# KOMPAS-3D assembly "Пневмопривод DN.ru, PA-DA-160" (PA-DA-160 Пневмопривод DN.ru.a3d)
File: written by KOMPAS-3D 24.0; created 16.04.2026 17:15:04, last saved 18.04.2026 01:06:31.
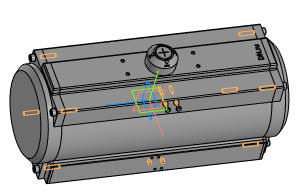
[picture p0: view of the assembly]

Document properties: Автор: DN.ru; Полное имя файла: C:\Работа\PA-DA-х Пневмопривод DN.ru\160\исходные материалы\PA-DA-160 Пневмопривод DN.ru.a3d

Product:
- Component [detail]: Пневмопривод DN.ru  | designation PA-DA-160  | qty 1  | pos. 1  | Масса: 20; Раздел спецификации: Прочие изделия; Примечание: D290-00299; Автор: DN.ru; source file: PA-DA-160 Пневмопривод DN.ru.m3d
- Component [standard]: Болт М5-6gx50 ГОСТ 7805-70  | qty 2  | Масса: 0.008999; Раздел спецификации: Стандартные изделия; Рассекать на разрезах: no
- Component [standard]: Гайка М5-6H ГОСТ 5915-70  | qty 2  | Масса: 0.00144; Раздел спецификации: Стандартные изделия; Рассекать на разрезах: no
- Component [standard]: Винт М8-6gx40 ГОСТ 11738-84  | qty 8  | Масса: 0.02082; Раздел спецификации: Стандартные изделия; Рассекать на разрезах: no
- Part/product: Пневмопривод DN.ru  | designation PA-DA-160
    Масса: 20
    Раздел спецификации: Прочие изделия
    Примечание: D290-00299

Expressions: D290-00299
Referenced files in C:\Работа\PA-DA-х Пневмопривод DN.ru\160\исходные материалы\: PA-DA-160 Пневмопривод DN.ru.m3d
Referenced files in C:\Program Files\ASCON\KOMPAS-3D v24\Libs\PolynomLib\DATA\vault\Methods\Kompas\3D\: PLib_Bolt_1_900.m3d, PLib_Nut_OST92_900.m3d, PLib_Screw_GOST_11738_1500.m3d
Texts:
  PA-DA-160
  Крепежное изделие ГОСТ
  BOSimple***PART:53acba15-081d-1c02-6810-072b309dd366***SHORTLOC:Root±30±20±10±80±10±©{}30±©{BASE}130±30[Нет;Без покрытия;Без указания материала;50;5;8;0,8;-]
  BOSimple***PART:0338bb82-6b79-df62-da33-8b23172f1b3e***SHORTLOC:Root±30±10±20±©{}110±10±50±60[Нет;Без покрытия;Без указания материала;-;5;0,8;8]
  BOSimple***PART:d807d535-b71f-aebb-1123-973396afaf10***SHORTLOC:Root±30±20±10±80±10±GMC90[Нет;Без покрытия;Без указания материала;1,25;-;40;8]
  Программные изделия  и базы данных
  PA-DA-160 Пневмопривод DN.ru
  Болт М5-6gx50 ГОСТ 7805-70 (1)
  hole1
  hole2
  Болт М5-6gx50 ГОСТ 7805-70 (2)
  Гайка М5-6H ГОСТ 5915-70 (1)
  bcut1
  hcut1
  cut1
  Гайка М5-6H ГОСТ 5915-70 (2)
  Винт М8-6gx40 ГОСТ 11738-84 (1)
  Винт М8-6gx40 ГОСТ 11738-84 (2)
  Винт М8-6gx40 ГОСТ 11738-84 (3)
  Винт М8-6gx40 ГОСТ 11738-84 (4)
  Винт М8-6gx40 ГОСТ 11738-84 (5)
  Винт М8-6gx40 ГОСТ 11738-84 (6)
  Винт М8-6gx40 ГОСТ 11738-84 (7)
  Винт М8-6gx40 ГОСТ 11738-84 (8)
  Plane. Начало координат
